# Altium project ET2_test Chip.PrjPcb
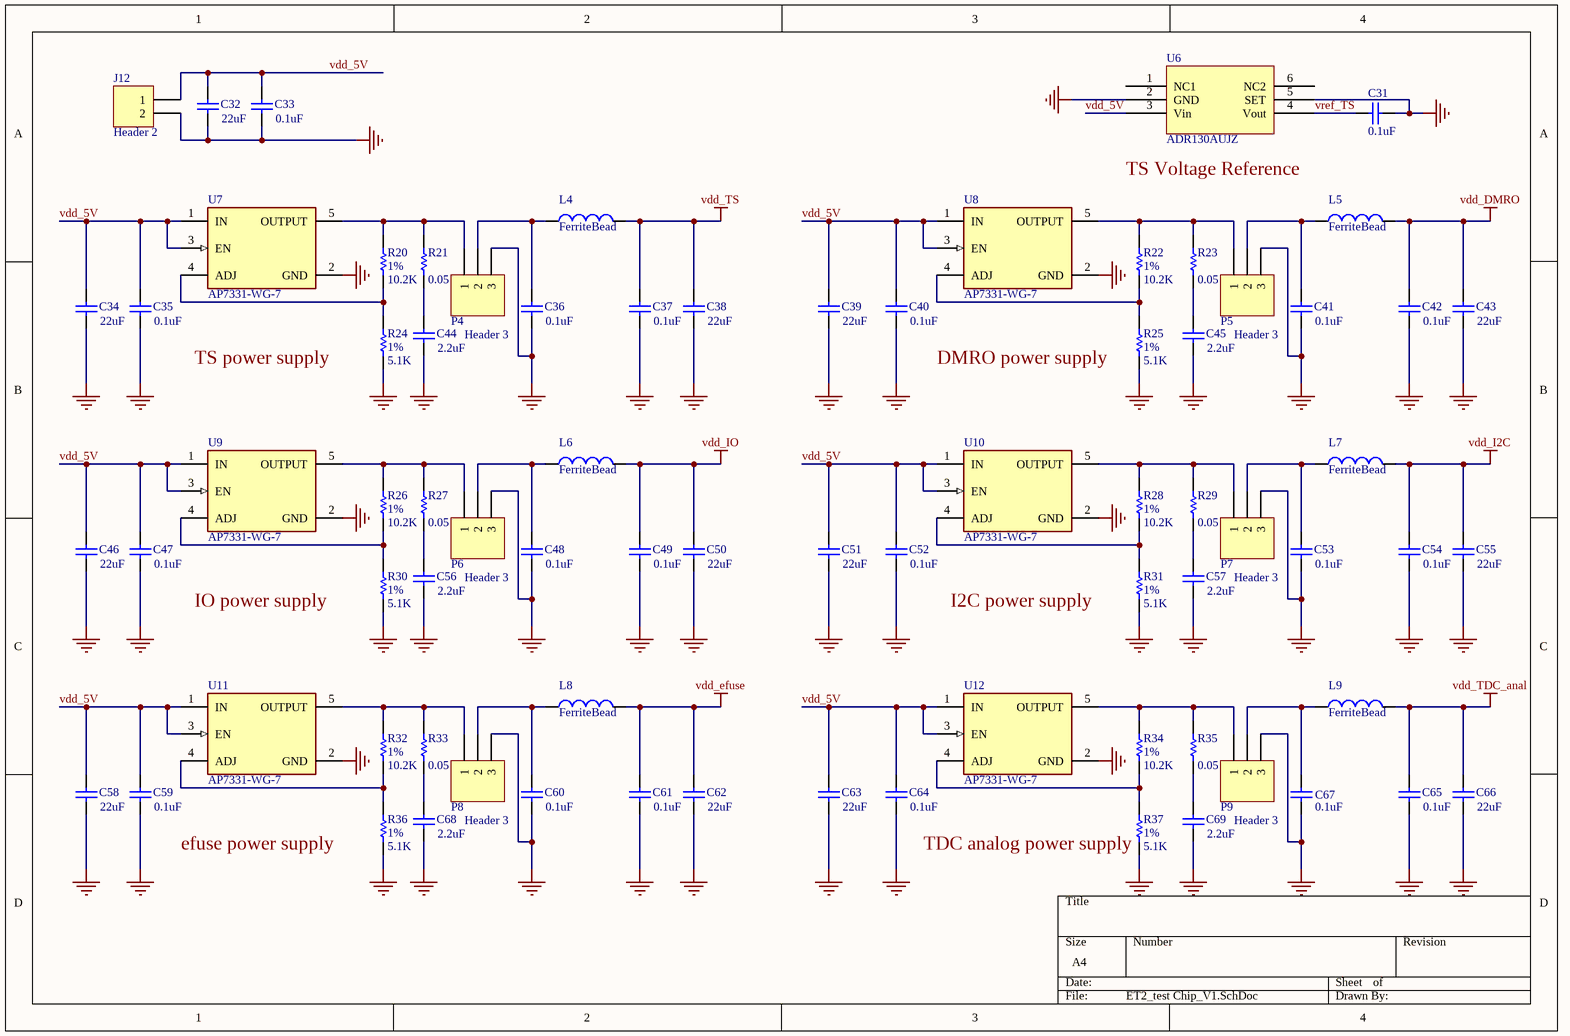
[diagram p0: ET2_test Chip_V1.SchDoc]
2 sheets, 148 parts. Net scope: global (net labels, ports and power ports of the same name join across sheets).
Board file: ET2_test Chip.PcbDoc
Sheets:
  ET2_test Chip_V1.SchDoc
  ET2_test_Chip.SchDoc

## Sheet ET2_test Chip_V1.SchDoc
size A4

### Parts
C31  value 0.1uF  [0402-eagle]  (hidden comment: Cap)
C32  value 22uF  [C1210]  (hidden comment: Cap)
C33  value 0.1uF  [0805-eagle]  (hidden comment: Cap)
C34  value 22uF  [C1210]  (hidden comment: Cap)
C35  value 0.1uF  [0805-eagle]  (hidden comment: Cap)
C36  value 0.1uF  [0805-eagle]  (hidden comment: Cap)
C37  value 0.1uF  [0805-eagle]  (hidden comment: Cap)
C38  value 22uF  [C1210]  (hidden comment: Cap)
C39  value 22uF  [C1210]  (hidden comment: Cap)
C40  value 0.1uF  [0805-eagle]  (hidden comment: Cap)
C41  value 0.1uF  [0805-eagle]  (hidden comment: Cap)
C42  value 0.1uF  [0805-eagle]  (hidden comment: Cap)
C43  value 22uF  [C1210]  (hidden comment: Cap)
C44  value 2.2uF  [0805-eagle]  (hidden comment: Cap)
C45  value 2.2uF  [0805-eagle]  (hidden comment: Cap)
C46  value 22uF  [C1210]  (hidden comment: Cap)
C47  value 0.1uF  [0805-eagle]  (hidden comment: Cap)
C48  value 0.1uF  [0805-eagle]  (hidden comment: Cap)
C49  value 0.1uF  [0805-eagle]  (hidden comment: Cap)
C50  value 22uF  [C1210]  (hidden comment: Cap)
C51  value 22uF  [C1210]  (hidden comment: Cap)
C52  value 0.1uF  [0805-eagle]  (hidden comment: Cap)
C53  value 0.1uF  [0805-eagle]  (hidden comment: Cap)
C54  value 0.1uF  [0805-eagle]  (hidden comment: Cap)
C55  value 22uF  [C1210]  (hidden comment: Cap)
C56  value 2.2uF  [0805-eagle]  (hidden comment: Cap)
C57  value 2.2uF  [0805-eagle]  (hidden comment: Cap)
C58  value 22uF  [C1210]  (hidden comment: Cap)
C59  value 0.1uF  [0805-eagle]  (hidden comment: Cap)
C60  value 0.1uF  [0805-eagle]  (hidden comment: Cap)
C61  value 0.1uF  [0805-eagle]  (hidden comment: Cap)
C62  value 22uF  [C1210]  (hidden comment: Cap)
C63  value 22uF  [C1210]  (hidden comment: Cap)
C64  value 0.1uF  [0805-eagle]  (hidden comment: Cap)
C65  value 0.1uF  [0805-eagle]  (hidden comment: Cap)
C66  value 22uF  [C1210]  (hidden comment: Cap)
C67  value 0.1uF  [0805-eagle]  (hidden comment: Cap)
C68  value 2.2uF  [0805-eagle]  (hidden comment: Cap)
C69  value 2.2uF  [0805-eagle]  (hidden comment: Cap)
J12  Header 2  [PowerJ2]
L4  value FerriteBead  [0805-eagle]  (hidden comment: Inductor)
L5  value FerriteBead  [0805-eagle]  (hidden comment: Inductor)
L6  value FerriteBead  [0805-eagle]  (hidden comment: Inductor)
L7  value FerriteBead  [0805-eagle]  (hidden comment: Inductor)
L8  value FerriteBead  [0805-eagle]  (hidden comment: Inductor)
L9  value FerriteBead  [0805-eagle]  (hidden comment: Inductor)
P4  Header 3  [Header3_L]
P5  Header 3  [Header3_L]
P6  Header 3  [Header3_L]
P7  Header 3  [Header3_L]
P8  Header 3  [Header3_L]
P9  Header 3  [Header3_L]
R20  1%  value 10.2K  [0402-eagle]
R21  value 0.05  [0402-eagle]  (hidden comment: 1%)
R22  1%  value 10.2K  [0402-eagle]
R23  value 0.05  [0402-eagle]  (hidden comment: 1%)
R24  1%  value 5.1K  [0402-eagle]
R25  1%  value 5.1K  [0402-eagle]
R26  1%  value 10.2K  [0402-eagle]
R27  value 0.05  [0402-eagle]  (hidden comment: 1%)
R28  1%  value 10.2K  [0402-eagle]
R29  value 0.05  [0402-eagle]  (hidden comment: 1%)
R30  1%  value 5.1K  [0402-eagle]
R31  1%  value 5.1K  [0402-eagle]
R32  1%  value 10.2K  [0402-eagle]
R33  value 0.05  [0402-eagle]  (hidden comment: 1%)
R34  1%  value 10.2K  [0402-eagle]
R35  value 0.05  [0402-eagle]  (hidden comment: 1%)
R36  1%  value 5.1K  [0402-eagle]
R37  1%  value 5.1K  [0402-eagle]
U6  ADR130AUJZ  [ADR130]
U7  AP7331-WG-7  [FP-SOT25-MFG]
U8  AP7331-WG-7  [FP-SOT25-MFG]
U9  AP7331-WG-7  [FP-SOT25-MFG]
U10  AP7331-WG-7  [FP-SOT25-MFG]
U11  AP7331-WG-7  [FP-SOT25-MFG]
U12  AP7331-WG-7  [FP-SOT25-MFG]

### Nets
GND: C31.1 C32.1 C33.1 C34.1 C35.1 C36.1 C37.1 C38.1 C39.1 C40.1 C41.1 C42.1 C43.1 C44.1 C45.1 C46.1 C47.1 C48.1 C49.1 C50.1 C51.1 C52.1 C53.1 C54.1 C55.1 C56.1 C57.1 C58.1 C59.1 C60.1 C61.1 C62.1 C63.1 C64.1 C65.1 C66.1 C67.1 C68.1 C69.1 J12.2 P4.3 P5.3 P6.3 P7.3 P8.3 P9.3 R24.1 R25.1 R30.1 R31.1 R36.1 R37.1 U6.2(GND) U6.5(SET) U7.2(GND) U8.2(GND) U9.2(GND) U10.2(GND) U11.2(GND) U12.2(GND)
vdd_DMRO: C42.2 C43.2 L5.2
vdd_efuse: C61.2 C62.2 L8.2
vdd_I2C: C54.2 C55.2 L7.2
vdd_IO: C49.2 C50.2 L6.2
vdd_TDC_anal: C65.2 C66.2 L9.2
vdd_TS: C37.2 C38.2 L4.2
vdd_5V: C32.2 C33.2 C34.2 C35.2 C39.2 C40.2 C46.2 C47.2 C51.2 C52.2 C58.2 C59.2 C63.2 C64.2 J12.1 U6.3(Vin) U7.1(IN) U7.3(EN) U8.1(IN) U8.3(EN) U9.1(IN) U9.3(EN) U10.1(IN) U10.3(EN) U11.1(IN) U11.3(EN) U12.1(IN) U12.3(EN)
vref_TS: C31.2 U6.4(Vout)
NetC36_2: C36.2 L4.1 P4.2
NetC41_2: C41.2 L5.1 P5.2
NetC44_2: C44.2 R21.1
NetC45_2: C45.2 R23.1
NetC48_2: C48.2 L6.1 P6.2
NetC53_2: C53.2 L7.1 P7.2
NetC56_2: C56.2 R27.1
NetC57_2: C57.2 R29.1
NetC60_2: C60.2 L8.1 P8.2
NetC67_2: C67.2 L9.1 P9.2
NetC68_2: C68.2 R33.1
NetC69_2: C69.2 R35.1
NetP4_1: P4.1 R20.2 R21.2 U7.5(OUTPUT)
NetP5_1: P5.1 R22.2 R23.2 U8.5(OUTPUT)
NetP6_1: P6.1 R26.2 R27.2 U9.5(OUTPUT)
NetP7_1: P7.1 R28.2 R29.2 U10.5(OUTPUT)
NetP8_1: P8.1 R32.2 R33.2 U11.5(OUTPUT)
NetP9_1: P9.1 R34.2 R35.2 U12.5(OUTPUT)
NetR20_1: R20.1 R24.2 U7.4(ADJ)
NetR22_1: R22.1 R25.2 U8.4(ADJ)
NetR26_1: R26.1 R30.2 U9.4(ADJ)
NetR28_1: R28.1 R31.2 U10.4(ADJ)
NetR32_1: R32.1 R36.2 U11.4(ADJ)
NetR34_1: R34.1 R37.2 U12.4(ADJ)

Not connected (* = marked no-connect by the designer): U6 1(NC1) 6(NC2)

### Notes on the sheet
- TS Voltage Reference
- TS power supply
- DMRO power supply
- IO power supply
- (near R31) I2C power supply
- (near R36) efuse power supply
- (near R37) TDC analog power supply

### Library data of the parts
C31-C69 = Cap: Capacitor
J12 = Header 2: Header, 2-Pin
L4-L9 = Inductor: Code_IEC: 1005
P4-P9 = Header 3: Header, 3-Pin
R20-R37 = Res1: Resistor
U6 = ADR130
U7-U12 = CMP-12756-000022-1: IC REG LIN POS ADJ 300MA SOT25; Manufacturer: Diodes Inc.; Dropout Voltage: 300mV; Nominal Supply Current: 55-65uA; Standoff Height: 0.013mm; Output Voltage: 0.8-5V; Min Supply Voltage: 2V; Number Of Outputs: 1; Max Supply Voltage: 6V; Output Type: AdjustableProgrammable; Accuracy Percentage: 2%; Max Junction Temp: +150°C; Max Power Dissipation: 640mW

## Sheet ET2_test_Chip.SchDoc: ET2_test Chip
size A4; Author: Wei Zhang
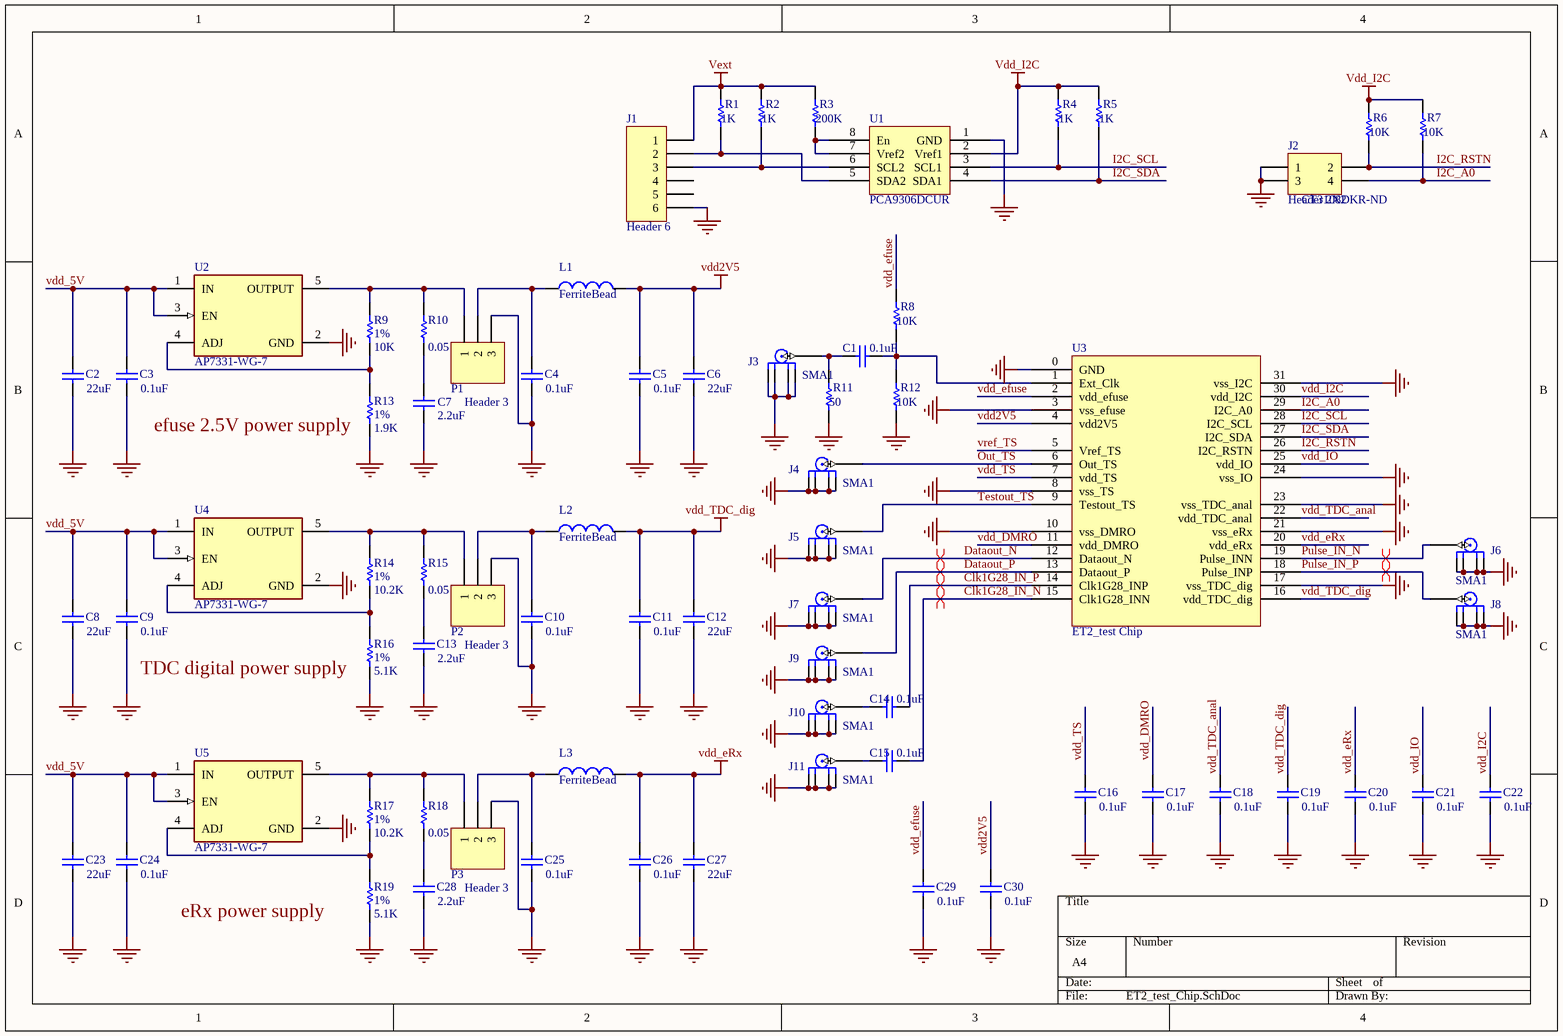
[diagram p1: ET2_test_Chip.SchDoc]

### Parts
C1  value 0.1uF  [0402-eagle]  (hidden comment: Cap)
C2  value 22uF  [C1210]  (hidden comment: Cap)
C3  value 0.1uF  [0805-eagle]  (hidden comment: Cap)
C4  value 0.1uF  [0805-eagle]  (hidden comment: Cap)
C5  value 0.1uF  [0805-eagle]  (hidden comment: Cap)
C6  value 22uF  [C1210]  (hidden comment: Cap)
C7  value 2.2uF  [0805-eagle]  (hidden comment: Cap)
C8  value 22uF  [C1210]  (hidden comment: Cap)
C9  value 0.1uF  [0805-eagle]  (hidden comment: Cap)
C10  value 0.1uF  [0805-eagle]  (hidden comment: Cap)
C11  value 0.1uF  [0805-eagle]  (hidden comment: Cap)
C12  value 22uF  [C1210]  (hidden comment: Cap)
C13  value 2.2uF  [0805-eagle]  (hidden comment: Cap)
C14  value 0.1uF  [0402-eagle]  (hidden comment: Cap)
C15  value 0.1uF  [0402-eagle]  (hidden comment: Cap)
C16  value 0.1uF  [0402-eagle]  (hidden comment: Cap)
C17  value 0.1uF  [0402-eagle]  (hidden comment: Cap)
C18  value 0.1uF  [0402-eagle]  (hidden comment: Cap)
C19  value 0.1uF  [0402-eagle]  (hidden comment: Cap)
C20  value 0.1uF  [0402-eagle]  (hidden comment: Cap)
C21  value 0.1uF  [0402-eagle]  (hidden comment: Cap)
C22  value 0.1uF  [0402-eagle]  (hidden comment: Cap)
C23  value 22uF  [C1210]  (hidden comment: Cap)
C24  value 0.1uF  [0805-eagle]  (hidden comment: Cap)
C25  value 0.1uF  [0805-eagle]  (hidden comment: Cap)
C26  value 0.1uF  [0805-eagle]  (hidden comment: Cap)
C27  value 22uF  [C1210]  (hidden comment: Cap)
C28  value 2.2uF  [0805-eagle]  (hidden comment: Cap)
C29  value 0.1uF  [0402-eagle]  (hidden comment: Cap)
C30  value 0.1uF  [0402-eagle]  (hidden comment: Cap)
J1  Header 6  [USB_ISS]
J2  Header 2X2  [HDR2X2]
J3  SMA1  [SMA_MID]
J4  SMA1  [SMA_MID]
J5  SMA1  [SMA_MID]
J6  SMA1  [SMA_MID]
J7  SMA1  [SMA_MID]
J8  SMA1  [SMA_MID]
J9  SMA1  [SMA_MID]
J10  SMA1  [SMA_MID]
J11  SMA1  [SMA_MID]
L1  value FerriteBead  [0805-eagle]  (hidden comment: Inductor)
L2  value FerriteBead  [0805-eagle]  (hidden comment: Inductor)
L3  value FerriteBead  [0805-eagle]  (hidden comment: Inductor)
P1  Header 3  [Header3_L]
P2  Header 3  [Header3_L]
P3  Header 3  [Header3_L]
R1  value 1K  [0402-eagle]  (hidden comment: Res1)
R2  value 1K  [0402-eagle]  (hidden comment: Res1)
R3  value 200K  [0402-eagle]  (hidden comment: Res1)
R4  value 1K  [0402-eagle]  (hidden comment: Res1)
R5  value 1K  [0402-eagle]  (hidden comment: Res1)
R6  value 10K  [0402-eagle]  (hidden comment: Res1)
R7  value 10K  [0402-eagle]  (hidden comment: Res1)
R8  value 10K  [0402-eagle]  (hidden comment: Res1)
R9  1%  value 10K  [0402-eagle]
R10  value 0.05  [0402-eagle]  (hidden comment: 1%)
R11  value 50  [0402-eagle]  (hidden comment: Res1)
R12  value 10K  [0402-eagle]  (hidden comment: Res1)
R13  1%  value 1.9K  [0402-eagle]
R14  1%  value 10.2K  [0402-eagle]
R15  value 0.05  [0402-eagle]  (hidden comment: 1%)
R16  1%  value 5.1K  [0402-eagle]
R17  1%  value 10.2K  [0402-eagle]
R18  value 0.05  [0402-eagle]  (hidden comment: 1%)
R19  1%  value 5.1K  [0402-eagle]
U1  PCA9306DCUR  [PCA9306]
U2  AP7331-WG-7  [FP-SOT25-MFG]
U3  ET2_test Chip
U4  AP7331-WG-7  [FP-SOT25-MFG]
U5  AP7331-WG-7  [FP-SOT25-MFG]

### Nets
GND: C2.1 C3.1 C4.1 C5.1 C6.1 C7.1 C8.1 C9.1 C10.1 C11.1 C12.1 C13.1 C16.1 C17.1 C18.1 C19.1 C20.1 C21.1 C22.1 C23.1 C24.1 C25.1 C26.1 C27.1 C28.1 C29.1 C30.1 J1.6 J2.1 J2.3 J3.2 J3.3 J3.4 J3.5 J4.2 J4.3 J4.4 J4.5 J5.2 J5.3 J5.4 J5.5 J6.2 J6.3 J6.4 J6.5 J7.2 J7.3 J7.4 J7.5 J8.2 J8.3 J8.4 J8.5 J9.2 J9.3 J9.4 J9.5 J10.2 J10.3 J10.4 J10.5 J11.2 J11.3 J11.4 J11.5 P1.3 P2.3 P3.3 R11.1 R12.1 R13.1 R16.1 R19.1 U1.1(GND) U2.2(GND) U3.0(GND) U3.3(vss_efuse) U3.8(vss_TS) U3.10(vss_DMRO) U3.17(vss_TDC_dig) U3.21(vss_eRx) U3.23(vss_TDC_anal) U3.24(vss_IO) U3.31(vss_I2C) U4.2(GND) U5.2(GND)
vdd2V5: C5.2 C6.2 C30.2 L1.2 U3.4(vdd2V5)
vdd_DMRO: C17.2 U3.11(vdd_DMRO)
vdd_efuse: C29.2 R8.2 U3.2(vdd_efuse)
vdd_eRx: C20.2 C26.2 C27.2 L3.2 U3.20(vdd_eRx)
vdd_I2C: C22.2 R4.2 R5.2 R6.2 R7.2 U1.2(Vref1) U3.30(vdd_I2C)
vdd_IO: C21.2 U3.25(vdd_IO)
vdd_TDC_anal: C18.2 U3.22(vdd_TDC_anal)
vdd_TDC_dig: C11.2 C12.2 C19.2 L2.2 U3.16(vdd_TDC_dig)
vdd_TS: C16.2 U3.7(vdd_TS)
Vext: J1.1 R1.2 R2.2 R3.2
Clk1G28_IN_N: C15.2 U3.15(Clk1G28_INN)
Clk1G28_IN_P: C14.2 U3.14(Clk1G28_INP)
Dataout_N: J7.1 U3.12(Dataout_N)
Dataout_P: J9.1 U3.13(Dataout_P)
I2C_A0: J2.4 R7.1 U3.29(I2C_A0)
I2C_RSTN: J2.2 R6.1 U3.26(I2C_RSTN)
I2C_SCL: R4.1 U1.3(SCL1) U3.28(I2C_SCL)
I2C_SDA: R5.1 U1.4(SDA1) U3.27(I2C_SDA)
Out_TS: J4.1 U3.6(Out_TS)
Pulse_IN_N: J6.1 U3.19(Pulse_INN)
Pulse_IN_P: J8.1 U3.18(Pulse_INP)
Testout_TS: J5.1 U3.9(Testout_TS)
vdd_5V: C2.2 C3.2 C8.2 C9.2 C23.2 C24.2 U2.1(IN) U2.3(EN) U4.1(IN) U4.3(EN) U5.1(IN) U5.3(EN)
vref_TS: U3.5(Vref_TS)
NetC1_1: C1.1 J3.1 R11.2
NetC1_2: C1.2 R8.1 R12.2 U3.1(Ext_Clk)
NetC4_2: C4.2 L1.1 P1.2
NetC7_2: C7.2 R10.1
NetC10_2: C10.2 L2.1 P2.2
NetC13_2: C13.2 R15.1
NetC14_1: C14.1 J10.1
NetC15_1: C15.1 J11.1
NetC25_2: C25.2 L3.1 P3.2
NetC28_2: C28.2 R18.1
NetJ1_2: J1.2 R1.1 U1.5(SDA2)
NetJ1_3: J1.3 R2.1 U1.6(SCL2)
NetP1_1: P1.1 R9.2 R10.2 U2.5(OUTPUT)
NetP2_1: P2.1 R14.2 R15.2 U4.5(OUTPUT)
NetP3_1: P3.1 R17.2 R18.2 U5.5(OUTPUT)
NetR3_1: R3.1 U1.7(Vref2) U1.8(En)
NetR9_1: R9.1 R13.2 U2.4(ADJ)
NetR14_1: R14.1 R16.2 U4.4(ADJ)
NetR17_1: R17.1 R19.2 U5.4(ADJ)

Not connected (* = marked no-connect by the designer): J1 4 5

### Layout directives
differential pair: Clk1G28_IN_N, Clk1G28_IN_P, Dataout_N, Dataout_P, Pulse_IN_N, Pulse_IN_P

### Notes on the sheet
- (near J2) CT3108DKR-ND
- (near R13) efuse 2.5V power supply
- (near R16) TDC digital power supply
- (near R19) eRx power supply

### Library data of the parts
C1-C30 = Cap: Capacitor
J1 = Header 6: Header, 6-Pin
J2 = Header 2X2: Header, 2-Pin, Dual row
L1-L3 = Inductor: Code_IEC: 1005
P1-P3 = Header 3: Header, 3-Pin
R1-R19 = Res1: Resistor
U1 = PCA9306
U2 U4 U5 = CMP-12756-000022-1: as U7 on sheet ET2_test Chip_V1

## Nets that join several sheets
GND: ET2_test Chip_V1 (60 pins), ET2_test_Chip (87 pins)
vdd_DMRO: ET2_test Chip_V1 (C42.2 C43.2 L5.2), ET2_test_Chip (C17.2 U3.11)
vdd_efuse: ET2_test Chip_V1 (C61.2 C62.2 L8.2), ET2_test_Chip (C29.2 R8.2 U3.2)
vdd_I2C: ET2_test Chip_V1 (C54.2 C55.2 L7.2), ET2_test_Chip (7 pins)
vdd_IO: ET2_test Chip_V1 (C49.2 C50.2 L6.2), ET2_test_Chip (C21.2 U3.25)
vdd_TDC_anal: ET2_test Chip_V1 (C65.2 C66.2 L9.2), ET2_test_Chip (C18.2 U3.22)
vdd_TS: ET2_test Chip_V1 (C37.2 C38.2 L4.2), ET2_test_Chip (C16.2 U3.7)
vdd_5V: ET2_test Chip_V1 (28 pins), ET2_test_Chip (12 pins)
vref_TS: ET2_test Chip_V1 (C31.2 U6.4), ET2_test_Chip (U3.5)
